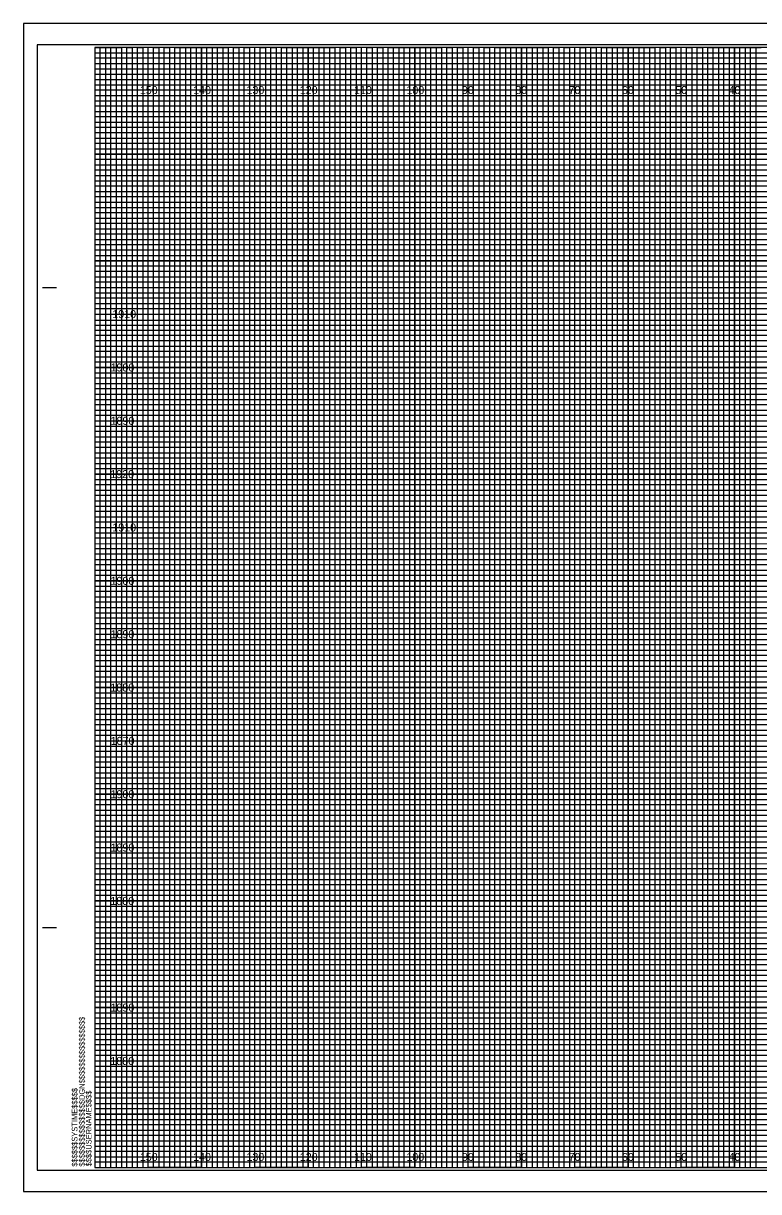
# Model space of a CAD drawing. Extents: x -13 to 323, y -4 to 214.
# Drawn here: x -13.4 to 124.5, y -4.5 to 214.5 of the extents above; entities that cross this region are included whole.
import ezdxf

# ---------------------------------------------------------------- set-up
doc = ezdxf.new("R2010")
doc.units = 0
for name, color, linetype in [('Prop XS Elevation Labels', 7, 'Continuous'), ('Prop XS Offset Labels', 7, 'Continuous'), ('Sheet Cross Section CELL', 7, 'Continuous'), ('Sheet Cross Section Grid Major CELL', 7, 'Continuous'), ('Sheet Cross Section Grid Middle CELL', 7, 'Continuous'), ('Sheet Cross Section Grid Minor 1 CELL', 7, 'Continuous'), ('Sheet Cross Section Grid Minor 2 CELL', 7, 'Continuous'), ('Sheet Cutting Line CELL', 7, 'Continuous'), ('Sheet DOT Grid CELL', 7, 'Continuous'), ('Sheet Plot Border Inside CELL', 7, 'Continuous'), ('Sheet Plot Border Outside CELL', 7, 'Continuous')]:
    doc.layers.add(name, color=color, linetype=linetype)

msp = doc.modelspace()

# ---------------------------------------------------------------- linework, layer by layer
at = {"layer": 'Sheet Cross Section CELL'}
for p, q in [((-9.8, 165), (-7.3, 165)), ((-9.7, 165), (-7.2, 165)), ((-9.8, 45), (-7.3, 45)), ((-9.7, 45), (-7.2, 45))]:
    msp.add_line(p, q, dxfattribs=at)
msp.add_lwpolyline([(320, 210), (0, 210), (0, 0), (320, 0)], close=True, dxfattribs=at)
at = {"layer": 'Sheet Cross Section Grid Major CELL'}
for p, q in [((10, 210), (0, 210)), ((10, 0), (10, 210)), ((30, 210), (20, 210)), ((20, 210), (20, 0)), ((30, 0), (30, 210)), ((50, 210), (40, 210)), ((40, 210), (40, 0)), ((50, 0), (50, 210)), ((70, 210), (60, 210)), ((60, 210), (60, 0)), ((70, 0), (70, 210)), ((90, 210), (80, 210)), ((80, 210), (80, 0)), ((90, 0), (90, 210)), ((110, 210), (100, 210)), ((100, 210), (100, 0)), ((110, 0), (110, 210)), ((130, 210), (120, 210)), ((120, 210), (120, 0)), ((20, 0), (10, 0)), ((40, 0), (30, 0)), ((60, 0), (50, 0)), ((80, 0), (70, 0)), ((100, 0), (90, 0)), ((120, 0), (110, 0))]:
    msp.add_line(p, q, dxfattribs=at)
for points in [[(0, 200), (320, 200), (320, 190), (0, 190)], [(0, 180), (320, 180), (320, 170), (0, 170)], [(0, 160), (320, 160), (320, 150), (0, 150)], [(0, 140), (320, 140), (320, 130), (0, 130)], [(0, 120), (320, 120), (320, 110), (0, 110)], [(0, 100), (320, 100), (320, 90), (0, 90)], [(0, 80), (320, 80), (320, 70), (0, 70)], [(0, 60), (320, 60), (320, 50), (0, 50)], [(0, 40), (320, 40), (320, 30), (0, 30)], [(0, 20), (320, 20), (320, 10), (0, 10)]]:
    msp.add_lwpolyline(points, dxfattribs=at)
at = {"layer": 'Sheet Cross Section Grid Middle CELL'}
for points in [[(0, 210), (5, 210), (5, 0), (15, 0), (15, 210), (25, 210), (25, 0), (35, 0), (35, 210), (45, 210), (45, 0), (55, 0), (55, 210), (65, 210), (65, 0), (75, 0), (75, 210), (85, 210), (85, 0), (95, 0), (95, 210), (105, 210), (105, 0), (115, 0), (115, 210), (125, 210)], [(0, 205), (275, 205)], [(0, 185), (320, 185), (320, 195), (0, 195)], [(0, 165), (320, 165), (320, 175), (0, 175)], [(0, 145), (320, 145), (320, 155), (0, 155)], [(0, 125), (320, 125), (320, 135), (0, 135)], [(0, 105), (320, 105), (320, 115), (0, 115)], [(0, 85), (320, 85), (320, 95), (0, 95)], [(0, 65), (320, 65), (320, 75), (0, 75)], [(0, 45), (320, 45), (320, 55), (0, 55)], [(0, 25), (320, 25), (320, 35), (0, 35)], [(0, 5), (320, 5), (320, 15), (0, 15)]]:
    msp.add_lwpolyline(points, dxfattribs=at)
at = {"layer": 'Sheet Cross Section Grid Minor 1 CELL'}
for p, q in [((0, 209), (260, 209)), ((260, 207.98), (0, 207.98)), ((0, 207.98), (0, 207)), ((0, 207), (260, 207)), ((260, 205.89), (0, 205.89)), ((0, 205.89), (0, 204)), ((0, 204), (320, 204))]:
    msp.add_line(p, q, dxfattribs=at)
for points in [[(0, 203), (270, 203), (320, 203), (320, 202), (0, 202)], [(0, 201), (320, 201), (320, 199), (0, 199)], [(0, 198), (320, 198), (320, 197), (0, 196.98)], [(0, 196), (320, 196), (320, 194), (0, 194)], [(0, 193), (320, 193), (320, 192), (0, 192)], [(0, 191), (320, 191), (320, 189), (0, 189)], [(0, 188), (320, 188), (320, 187), (0, 187)], [(0, 186), (320, 186), (320, 184), (0, 184)], [(0, 183), (320, 183), (320, 182), (0, 182)], [(0, 181), (320, 181), (320, 179), (0, 179)], [(0, 178), (320, 178), (320, 177), (0, 177)], [(0, 176), (320, 176), (320, 173.95), (320, 173), (320, 172), (0, 172)], [(0, 174), (320, 174), (320, 173), (0, 173)], [(0, 171), (320, 171), (320, 169), (0, 169.03)], [(0, 169.03), (320, 169), (320, 168), (0, 168)], [(0, 167), (320, 167), (320, 166), (0, 166)], [(0, 164), (320, 164), (320, 163), (0, 163)], [(0, 162), (320, 162), (320, 161), (0, 161)], [(-0.07, 158.89), (320, 158.89), (320, 157.88), (-0.07, 157.88)], [(0, 157), (320, 157), (320, 156), (0, 156)], [(0, 154), (320, 154), (320, 153), (0, 153)], [(0, 152), (320, 152), (320, 151), (0, 151)], [(0, 149), (320, 149), (320, 148), (0, 148)], [(0, 147), (320, 147), (320, 146), (0, 146)], [(0, 144), (320, 144), (320, 143), (0, 143)], [(0, 142), (320, 142), (320, 141), (0, 141)], [(0, 139), (320, 139), (319.99, 137.98), (0, 138)], [(0, 137), (320, 137), (320, 136), (0, 136)], [(0, 134), (320, 134), (320, 133), (0, 133)], [(0, 132), (320, 132), (320, 131), (0, 131)], [(0, 129), (320, 129), (320, 128), (0, 128)], [(0, 127), (320, 127), (320, 126), (0, 126)], [(0, 124), (320, 124), (320, 123), (0, 123)], [(0, 122), (320, 122), (320, 121), (0, 121)], [(0, 119), (320, 119), (320, 118), (0, 118)], [(0, 116.99), (320.07, 116.91), (320, 116), (0, 116)], [(0, 114), (320, 114), (320, 113), (0, 113)], [(0, 112), (320, 112), (320, 111), (0, 111)], [(0, 109), (320, 109), (320, 108), (0, 108)], [(0, 107), (320, 107), (320, 106), (0, 106)], [(0, 104), (320, 104), (320, 103), (0, 103)], [(0, 102), (320, 102), (320, 101), (0, 101)], [(0, 99), (320, 99), (320, 98), (0, 98)], [(0, 97), (320, 97), (320, 96), (0, 96)], [(0, 94), (320, 94), (320, 93), (0, 93)], [(0, 92), (320, 92), (320, 91), (0, 91)], [(0, 89), (320, 89), (320, 88), (0, 88)], [(0, 87), (320, 87), (320, 86), (0, 86)], [(0, 84), (320, 84), (320, 83), (0, 83)], [(0, 82), (320, 82), (320, 81), (0, 81)], [(0, 79), (320, 79), (319.99, 77.98), (0, 78)], [(0, 77), (320, 77), (320, 76), (0, 76)], [(0, 74), (320, 74), (320, 73), (0, 73)], [(0, 72), (320, 72), (320, 71), (0, 71)], [(0, 69), (320, 69), (320, 68), (0, 68)], [(0, 67), (320, 67), (320, 66), (0, 66)], [(0, 64), (320, 64), (320, 63), (0, 63)], [(0, 62), (320, 62), (320, 61), (0, 61)], [(0, 59), (320, 59), (320, 58), (0, 58)], [(0, 56.99), (320.07, 56.91), (320, 56), (0, 56)], [(0, 54), (320, 54), (320, 53), (0, 53)], [(0, 52), (320, 52), (320, 51), (0, 51)], [(0, 49), (320, 49), (320, 48), (0, 48)], [(0, 47), (320, 47), (320, 46), (0, 46)], [(0, 44), (320, 44), (320, 43), (0, 43)], [(0, 42), (320, 42), (320, 41), (0, 41)], [(0, 39), (320, 39), (320, 38), (0, 38)], [(0, 37), (320, 37), (320, 36), (0, 36)], [(0, 34), (320, 34), (320, 33), (0, 33)], [(0, 32), (320, 32), (320, 31), (0, 31)], [(0, 29), (320, 29), (320, 28), (0, 28)], [(0, 27), (320, 27), (320, 26), (0, 26)], [(0, 24), (320, 24), (320, 23), (0, 23)], [(0, 22), (320, 22), (320, 21), (0, 21)], [(0, 19), (320, 19), (320, 18), (0, 18)], [(0, 17), (320, 17), (320, 16), (0, 16)], [(0, 14), (320, 14), (320, 13), (0, 13)], [(0, 12), (320, 12), (320, 11), (0, 11)], [(0, 9), (320, 9), (320, 8), (0, 8)], [(0, 7), (320, 7), (320, 6), (0, 6)], [(0, 4), (320, 4), (320, 3), (0, 3)], [(0, 2), (320, 2), (320, 1), (0, 1)]]:
    msp.add_lwpolyline(points, dxfattribs=at)
at = {"layer": 'Sheet Cross Section Grid Minor 2 CELL'}
for points in [[(0, 0), (1, 0), (1, 210), (2, 210), (2, 0)], [(2, 0), (3, 0), (3, 210), (4, 210), (4, 0)], [(5, 0), (6, 0), (6, 210), (7, 210), (7, 0)], [(7, 0), (8, 0), (8, 210), (9, 210), (9, 0)], [(10, 0), (11, 0), (11, 210), (12, 210), (12, 0)], [(12, 0), (13, 0), (13, 210), (14, 210), (14, 0)], [(15, 0), (16, 0), (16, 210), (17, 210), (17, 0)], [(17, 0), (18, 0), (18, 210), (19, 210), (19, 0)], [(20, 0), (21, 0), (21, 210), (22, 210), (22, 0)], [(22, 0), (23, 0), (23, 210), (24, 210), (24, 0)], [(25, 0), (26, 0), (26, 210), (27, 210), (27, 0)], [(27, 0), (28, 0), (28, 210), (29, 210), (29, 0)], [(30, 0), (31, 0), (31, 210), (32, 210), (32, 0)], [(32, 0), (33, 0), (33, 210), (34, 210), (34, 0)], [(35, 0), (36, 0), (36, 210), (37, 210), (37, 0)], [(37, 0), (38, 0), (38, 210), (39, 210), (39, 0)], [(40, 0), (41, 0), (41, 210), (42, 210), (42, 0)], [(42, 0), (43, 0), (43, 210), (44, 210), (44, 0)], [(45, 0), (46, 0), (46, 210), (47, 210), (47, 0)], [(47, 0), (48, 0), (48, 210), (49, 210), (49, 0)], [(50, 0), (51, 0), (51, 210), (52, 210), (52, 0)], [(52, 0), (53, 0), (53, 210), (54, 210), (54, 0)], [(55, 0), (56, 0), (56, 210), (57, 210), (57, 0)], [(57, 0), (58, 0), (58, 210), (59, 210), (59, 0)], [(60, 0), (61, 0), (61, 210), (62, 210), (62, 0)], [(62, 0), (63, 0), (63, 210), (64, 210), (64, 0)], [(65, 0), (66, 0), (66, 210), (67, 210), (67, 0)], [(67, 0), (68, 0), (68, 210), (69, 210), (69, 0)], [(70, 0), (71, 0), (71, 210), (72, 210), (72, 0)], [(72, 0), (73, 0), (73, 210), (74, 210), (74, 0)], [(75, 0), (76, 0), (76, 210), (77, 210), (77, 0)], [(77, 0), (78, 0), (78, 210), (79, 210), (79, 0)], [(80, 0), (81, 0), (81, 210), (82, 210), (82, 0)], [(82, 0), (83, 0), (83, 210), (84, 210), (84, 0)], [(85, 0), (86, 0), (86, 210), (87, 210), (87, 0)], [(87, 0), (88, 0), (88, 210), (89, 210), (89, 0)], [(90, 0), (91, 0), (91, 210), (92, 210), (92, 0)], [(92, 0), (93, 0), (93, 210), (94, 210), (94, 0)], [(95, 0), (96, 0), (96, 210), (97, 210), (97, 0)], [(97, 0), (98, 0), (98, 210), (99, 210), (99, 0)], [(100, 0), (101, 0), (101, 210), (102, 210), (102, 0)], [(102, 0), (103, 0), (103, 210), (104, 210), (104, 0)], [(105, 0), (106, 0), (106, 210), (107, 210), (107, 0)], [(107, 0), (108, 0), (108, 210), (109, 210), (109, 0)], [(110, 0), (111, 0), (111, 210), (112, 210), (112, 0)], [(112, 0), (113, 0), (113, 210), (114, 210), (114, 0)], [(115, 0), (116, 0), (116, 210), (117, 210), (117, 0)], [(117, 0), (118, 0), (118, 210), (119, 210), (119, 0)], [(120, 0), (121, 0), (121, 210), (122, 210), (122, 0)], [(122, 0), (123, 0), (123, 210), (124, 210), (124, 0)]]:
    msp.add_lwpolyline(points, dxfattribs=at)
at = {"layer": 'Sheet Cutting Line CELL'}
for p, q in [((323.3, 214.5), (-13.4, 214.5)), ((-13.4, 214.5), (-13.4, -4.5)), ((-13.4, -4.5), (323.3, -4.5))]:
    msp.add_line(p, q, dxfattribs=at)
at = {"layer": 'Sheet DOT Grid CELL'}
for p, q in [((10, 0), (10, 210)), ((20, 0), (20, 210)), ((30, 0), (30, 210)), ((40, 0), (40, 210)), ((50, 0), (50, 210)), ((60, 0), (60, 210)), ((70, 0), (70, 210)), ((80, 0), (80, 210)), ((90, 0), (90, 210)), ((100, 0), (100, 210)), ((110, 0), (110, 210)), ((120, 0), (120, 210)), ((0, 200), (320, 200)), ((0, 190), (320, 190)), ((0, 180), (320, 180)), ((0, 170), (320, 170)), ((0, 160), (320, 160)), ((0, 150), (320, 150)), ((0, 140), (320, 140)), ((0, 130), (320, 130)), ((0, 120), (320, 120)), ((0, 110), (320, 110)), ((0, 100), (320, 100)), ((0, 90), (320, 90)), ((0, 80), (320, 80)), ((0, 70), (320, 70)), ((0, 60), (320, 60)), ((0, 50), (320, 50)), ((0, 40), (320, 40)), ((0, 30), (320, 30)), ((0, 20), (320, 20)), ((0, 10), (320, 10))]:
    msp.add_line(p, q, dxfattribs=at)
at = {"layer": 'Sheet Plot Border Inside CELL'}
msp.add_lwpolyline([(-10.8, -0.5), (322.4, -0.5), (322.4, 210.5), (-10.8, 210.5)], close=True, dxfattribs=at)
at = {"layer": 'Sheet Plot Border Outside CELL'}
msp.add_lwpolyline([(-13.4, -4.5), (323.3, -4.5), (323.3, 214.5), (-13.4, 214.5)], close=True, dxfattribs=at)

# ---------------------------------------------------------------- texts
at = {"layer": 'Prop XS Elevation Labels'}
for s, p in [('1910', (3.28, 159.25)), ('1900', (2.95, 149.25)), ('1890', (2.95, 139.25)), ('1920', (2.9, 129.25)), ('1910', (3.28, 119.25)), ('1900', (2.95, 109.25)), ('1890', (2.95, 99.25)), ('1880', (2.92, 89.25)), ('1870', (2.98, 79.25)), ('1900', (2.95, 69.25)), ('1890', (2.95, 59.25)), ('1880', (2.92, 49.25)), ('1890', (2.95, 29.25)), ('1880', (2.92, 19.25))]:
    msp.add_text(s, height=1.5, dxfattribs=at).set_placement(p)
at = {"layer": 'Prop XS Offset Labels'}
for s, p in [('150', (8.44, 201.25)), ('140', (18.44, 201.25)), ('130', (28.44, 201.25)), ('120', (38.44, 201.25)), ('110', (48.62, 201.25)), ('100', (58.44, 201.25)), ('90', (68.86, 201.25)), ('80', (78.86, 201.25)), ('70', (88.86, 201.25)), ('60', (98.86, 201.25)), ('50', (108.86, 201.25)), ('40', (118.86, 201.25)), ('150', (8.44, 1.25)), ('140', (18.44, 1.25)), ('130', (28.44, 1.25)), ('120', (38.44, 1.25)), ('110', (48.62, 1.25)), ('100', (58.44, 1.25)), ('90', (68.86, 1.25)), ('80', (78.86, 1.25)), ('70', (88.86, 1.25)), ('60', (98.86, 1.25)), ('50', (108.86, 1.25)), ('40', (118.86, 1.25))]:
    msp.add_text(s, height=1.5, dxfattribs=at).set_placement(p)
at = {"layer": 'Sheet Cross Section CELL'}
for s, p in [('$$$$$$$$$$$$$$$$DGN$$$$$$$$$$$$$$$$', (-1.88, 0.18)), ('$$$$$$SYSTIME$$$$$', (-3.26, 0.18)), ('$$$$USERNAME$$$$', (-0.62, 0.23))]:
    msp.add_text(s, height=1.05, rotation=90, dxfattribs=at).set_placement(p)

doc.saveas('drawing.dxf')
